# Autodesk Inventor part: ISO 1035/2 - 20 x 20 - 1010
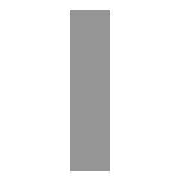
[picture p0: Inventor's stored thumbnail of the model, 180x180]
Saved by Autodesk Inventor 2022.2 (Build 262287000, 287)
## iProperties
IsCustomPart: 1
Created: 2025-02
Part Number: ISO 1035/2 - 20 x 20 - 1010
Material: Acciaio, Dolce
Description: Barre in acciaio laminate a caldo - Parte 2: barre quadre
Document SubType Name: Modeling
Standard: ISO 1035/2
Designer: 18907419
Standard Revision: First edition 1980-10-15
Standards Organization: ISO
Language: it-IT
Size Designation: 20x 20
Categories: <MemberInstance><Categories><Category DisplayName="Forme strutturali" InternalName="089c4875-fa83-4c05-b084-43b9cc11f5ed" Mnemonic="GRDR"><CategoryParameter Dis
Stock Number: 20x 20
Density: 7.85 g/cm^3
Appearance: Semilucidato
_CCFamilyMember: 168
_CCFamilyDisplayName: ISO 1035/2 - 1980 - Barre in acciaio laminate a caldo - Parte 2: barre quadre
_FrameMemberDoc: Frame Member File
_Version: 15.0.0
_GetPNFromCC: 1
G_L: 1010,000 mm
G_W: 20,000 mm
G_H: 20,000 mm
+520B30BA-A766-466E-8C54-70492AFF0E80+CUTDETAIL1: Angolo retto 45,00 gr
+D8BF1E54-B56E-453A-8C5C-CEB3DD3A30D1+CUTDETAIL2: Angolo retto 45,00 gr
Author: 18907419
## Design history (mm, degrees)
node "Piano iniziale"
node "Piano finale"
sketch "Schizzo"
  geometry: L1 (10, -10)-(-10, -10); L2 (-10, -10)-(-10, 10); L3 (-10, 10)-(10, 10); L4 (10, 10)-(10, -10); L5 (-6, 0)-(8, 0); L6 (0, -30)-(0, 40); L7 (0, 54)-(0, -44) reference; L8 (-14, 0)-(14, 0) reference
  constraints: 12 end point, 2 collinear, 2 parallel, 1 horizontal, 1 perpendicular
  dimensions: "d0" = 20 distance between parallel lines of L3 L1 (= G_W); "d1" = 20 distance between parallel lines of L4 L2 (= G_H); "d4" = 10 distance between parallel lines of L6 L4 (= 0.5 x d1); "d5" = 10 distance between parallel lines of L5 L3 (= 0.5 x d0)
extrude "Corpo" new body sketch "Schizzo" stored distance "d2" = 1010 (= G_L); taper "d3" = 0 deg
node "Driven Length"
  sketch "Sketch3"
    geometry: L1 (0, 0)-(10, 0) reference
    constraints: 2 end point, 1 horizontal
  workplane "Work Plane3"
  sketch "Sketch4"
    geometry: L1 (-2, -10)-(12, -10) reference; L2 (-2, 1000)-(12, 1000) reference
    dimensions: "d9" = 1010 dimension on L1 L2 (derived)
node "Piano di lavoro4"
feature "Divisione1"
node "Piano di lavoro5"
feature "Divisione2"
body "Solid1"
other parameters: "G_W" = 20 [user parameter; used in 1 equation term], "G_H" = 20 [user parameter; used in 1 equation term], "G_L" = 1010 (= d9) [user parameter; used in 1 equation term], "G_OFFSET_END" = 0 [user parameter; used in 1 equation term], "d8" = 90 deg
